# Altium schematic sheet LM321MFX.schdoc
size 127 x 101 mm
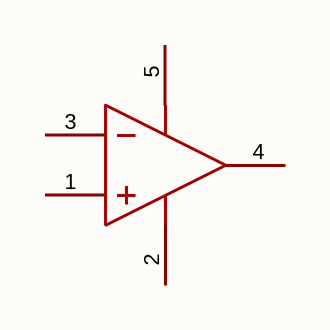
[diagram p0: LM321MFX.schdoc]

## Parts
U?  lm321mfx  [SOT-23-5_L2.9-W1.6-P0.95-LS2.8-BL]  (value not drawn)

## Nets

Not connected (* = marked no-connect by the designer): U? 1(+IN) 2(-VS) 3(-IN) 4(OUT) 5(+VS)

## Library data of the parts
U? = lm321mfx: 放大器数:1;轨到轨:-;增益带宽积(GBW):-;输入失调电压(Vos):11mV;压摆率(SR):-;输入偏置电流(Ib):250nA;; Manufacturer: TECH PUBLIC(台舟); AddInBom: yes; ModelId: 018c57e721114987ae90467fe9f1d259; ModelTransform: 114.96,110.236,0,0,0,0,0,0,0; Number of Channels: 1; Maximum Power Supply Range (Vdd-Vss): 36V; Vos - Input Offset Voltage: 11mV; Input Offset Voltage Drift(Vos TC): 50uV/℃; Ib - Input Bias Current: 250nA; Input Offset Current(Ios): 2nA; Common Mode Rejection Ratio(CMRR): 80dB; Input offset current drift(Ios TC): 10pA/℃; Quiescent Current: 700uA; Output Current: 20mA; Single supply: 3V~36V; Dual Supply: -20V~20V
